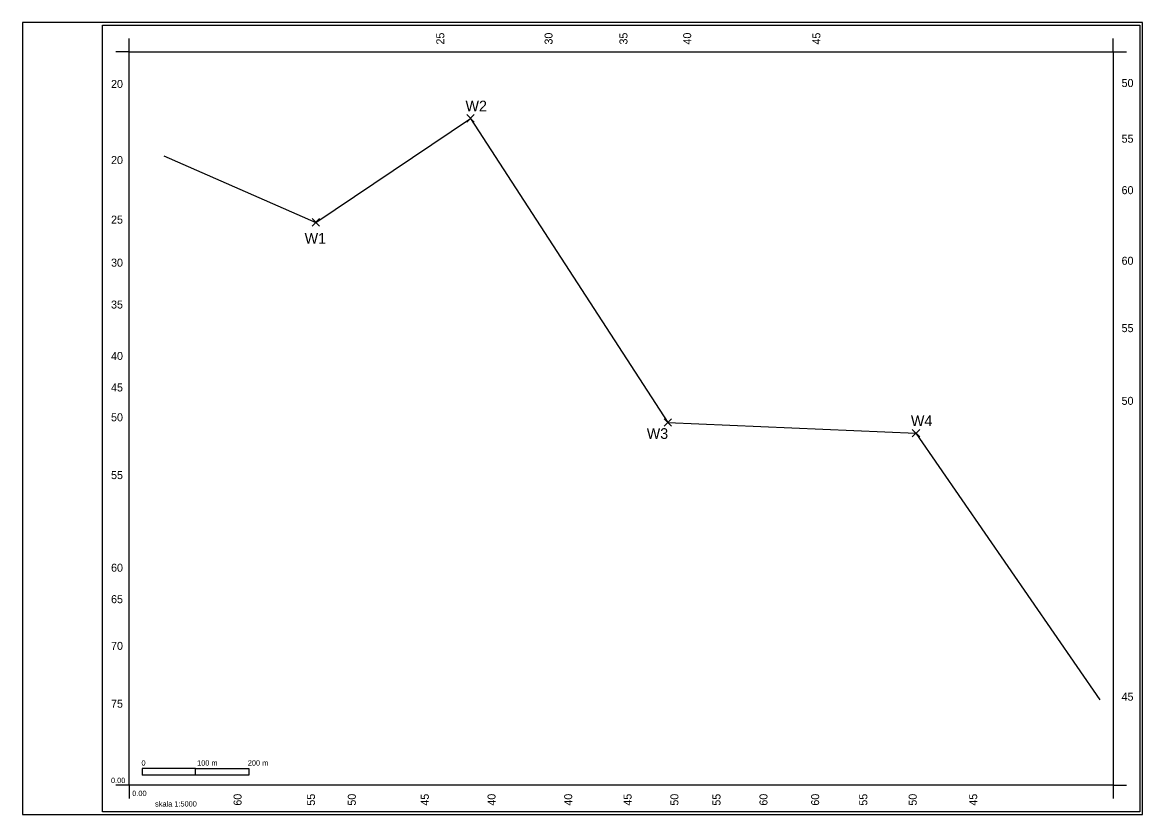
# Model space of a CAD drawing. Extents: x -200 to 1900, y -55 to 1430.
import ezdxf

# ---------------------------------------------------------------- set-up
doc = ezdxf.new("R2010")
doc.units = 0
doc.layers.add('Domyślna', color=7, linetype='Continuous')
doc.layers.add('trasa1', color=7, linetype='Continuous')

msp = doc.modelspace()

# ---------------------------------------------------------------- linework, layer by layer
at = {"layer": 'Domyślna'}
for p, q in [((0, 1375), (0, 1400)), ((1845, 1375), (1845, 1400)), ((0, 1375), (-25, 1375)), ((1845, 1375), (1870, 1375)), ((124.3, 31.4), (24.3, 31.4)), ((24.3, 31.4), (24.3, 18.9)), ((124.3, 18.9), (24.3, 18.9)), ((0, 0), (-25, 0)), ((0, 0), (0, -25)), ((1845, 0), (1845, -25)), ((1845, 0), (1870, 0))]:
    msp.add_line(p, q, dxfattribs=at)
for points in [[(-200, -55), (1900, -55), (1900, 1430), (-200, 1430)], [(-50, -50), (-50, 1425), (1895, 1425), (1895, -50)], [(0, 1375), (1845, 1375), (1845, 0), (0, 0)], [(224.3, 18.9), (124.3, 18.9), (124.3, 31.4), (224.3, 31.4)]]:
    msp.add_lwpolyline(points, close=True, dxfattribs=at)
at = {"layer": 'trasa1'}
for p, q in [((632.9, 1257.1), (647.1, 1242.9)), ((647.1, 1257.1), (632.9, 1242.9)), ((342.9, 1062.1), (357.1, 1047.9)), ((357.1, 1062.1), (342.9, 1047.9)), ((1002.9, 687.1), (1017.1, 672.9)), ((1017.1, 687.1), (1002.9, 672.9)), ((1467.9, 667.1), (1482.1, 652.9)), ((1482.1, 667.1), (1467.9, 652.9))]:
    msp.add_line(p, q, dxfattribs=at)
msp.add_lwpolyline([(65, 1180), (350, 1055), (640, 1250), (1010, 680), (1475, 660), (1820, 160)], dxfattribs=at)

# ---------------------------------------------------------------- texts
at = {"layer": 'Domyślna'}
for s, p in [('25', (590.9, 1388.5)), ('30', (793.9, 1388.5)), ('35', (934.3, 1388.5)), ('40', (1053.8, 1388.5)), ('45', (1295.9, 1388.5)), ('60', (210.9, -38.2)), ('55', (348.4, -38.2)), ('50', (425, -38.2)), ('45', (561.9, -38.2)), ('40', (687, -38.2)), ('40', (830.7, -38.2)), ('45', (942, -38.2)), ('50', (1029.8, -38.2)), ('55', (1108.7, -38.2)), ('60', (1196.8, -38.2)), ('60', (1293.7, -38.2)), ('55', (1383.9, -38.2)), ('50', (1476.5, -38.2)), ('45', (1589.9, -38.2))]:
    msp.add_text(s, height=15, rotation=90, dxfattribs=at).set_placement(p)
for s, height, p in [('50', 15, (1860.6, 1308.9)), ('20', 15, (-33.8, 1307.1)), ('55', 15, (1860.6, 1204.5)), ('20', 15, (-33.8, 1164.5)), ('60', 15, (1860.6, 1108)), ('25', 15, (-33.8, 1052.8)), ('30', 15, (-33.8, 972.1)), ('60', 15, (1860.6, 975.7)), ('35', 15, (-33.8, 893.6)), ('55', 15, (1860.6, 849.4)), ('40', 15, (-33.8, 797.2)), ('45', 15, (-33.8, 738.2)), ('50', 15, (1860.6, 713.1)), ('50', 15, (-33.8, 682.3)), ('55', 15, (-33.8, 573.9)), ('60', 15, (-33.8, 400.3)), ('65', 15, (-33.8, 341.3)), ('70', 15, (-33.8, 253.8)), ('45', 15, (1860.6, 158.6)), ('75', 15, (-33.8, 145.4)), ('0', 10, (23.2, 36.8)), ('100 m', 10, (127.5, 36.8)), ('200 m', 10, (222.5, 36.8)), ('0.00', 10, (-33.9, 4.1)), ('0.00', 10, (5.9, -20.2)), ('skala 1:5000', 10, (48.7, -39.9))]:
    msp.add_text(s, height=height, dxfattribs=at).set_placement(p)
at = {"layer": 'trasa1'}
for s, p in [('W2', (630.7, 1263.3)), ('W1', (329.1, 1015.2)), ('W4', (1465.7, 673.3)), ('W3', (970.5, 649.3))]:
    msp.add_text(s, height=20, dxfattribs=at).set_placement(p)

doc.saveas('drawing.dxf')
